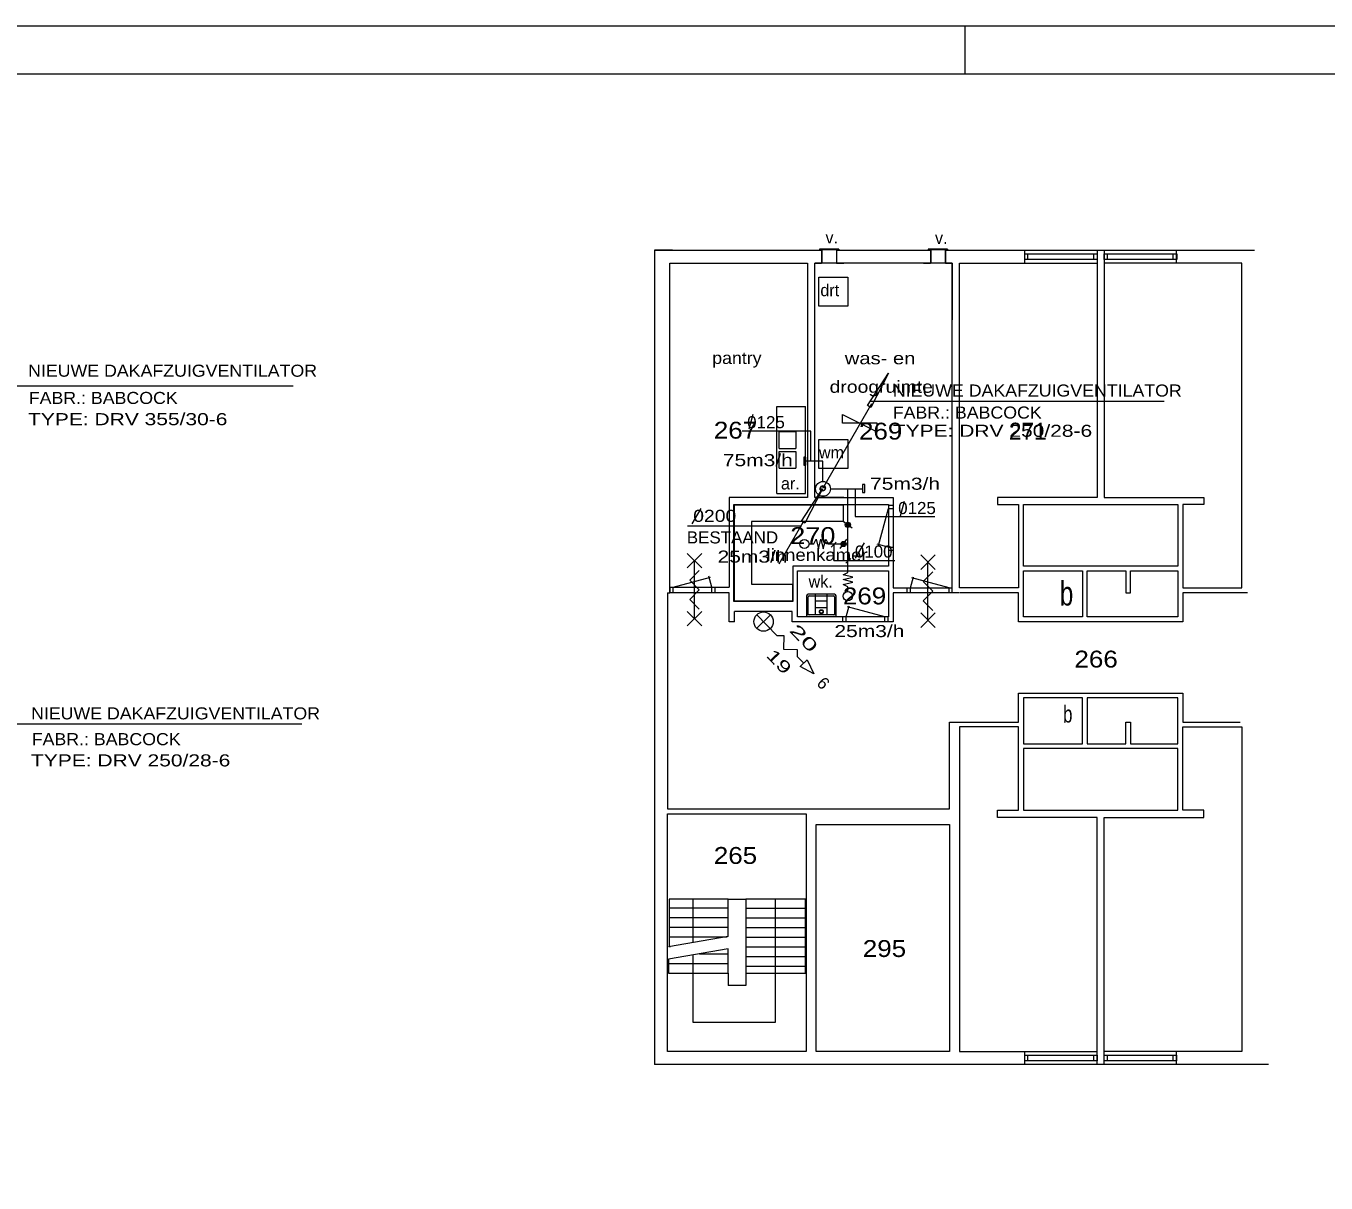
# Model space of a CAD drawing. Extents: x 295824 to 414724, y 24924 to 109024.
# Drawn here: x 332262 to 359197, y 85056 to 109024 of the extents above; entities that cross this region are included whole.
import ezdxf
from ezdxf.enums import TextEntityAlignment as Align

# ---------------------------------------------------------------- set-up
doc = ezdxf.new("R2010")
doc.units = 0
doc.header["$LTSCALE"] = 100
for name, color, linetype, lineweight in [('1', 7, 'Continuous', 13), ('24', 7, 'Continuous', 13), ('61', 7, 'Continuous', 13)]:
    doc.layers.add(name, color=color, linetype=linetype, lineweight=lineweight)

msp = doc.modelspace()

# ---------------------------------------------------------------- hatches: boundary and pattern name
at = {"layer": '24'}
for points in [[(349236.3, 98689.8, 1), (349344.9, 98689.8, 1)], [(349201, 98347.3, 1), (349201, 98238.7, 1)]]:
    msp.add_hatch(color=256, dxfattribs=at).paths.add_polyline_path(points)

# ---------------------------------------------------------------- linework, layer by layer
at = {"layer": '1'}
for p, q in [((351723.6, 108023.8), (351723.6, 109023.8)), ((347864.2, 97878.8), (348364.2, 98744.8))]:
    msp.add_line(p, q, dxfattribs=at)
for points in [[(414723.6, 109023.8), (304995.6, 109023.8), (295823.6, 109023.8)], [(304995.6, 25923.8), (413723.6, 25923.8), (413723.6, 108023.8), (304995.6, 108023.8)]]:
    msp.add_lwpolyline(points, dxfattribs=at)
msp.add_lwpolyline([(348764.2, 99437.8), (348400.2, 98723.8), (348328.2, 98765.8)], close=True, dxfattribs=at)
for centre in [(348764.2, 99437.5), (348777, 99453.9)]:
    msp.add_circle(centre, 50, dxfattribs=at)
at = {"layer": '24'}
for p, q in [((329942.6, 101572.7), (337794.9, 101572.7)), ((348777, 99454.2), (349787.6, 101204.5)), ((349752.7, 101252.7), (355843, 101252.7)), ((347322.1, 100977.4), (347240, 100670.9)), ((348774.2, 100005.9), (348418.4, 100005.9)), ((348774.2, 99588.7), (348774.2, 100005.9)), ((348927.8, 99435.2), (349590.4, 99435.2)), ((349290.6, 97754.4), (349290.6, 99435.2)), ((350459, 99175.8), (350376.9, 98869.3)), ((346240.6, 99028.4), (346056.3, 98709.1)), ((345969.4, 98666.6), (348330.2, 98666.6)), ((349382.2, 98619), (349190.6, 98760.6)), ((349047.8, 98330), (348945.6, 98227.8)), ((349130.2, 98201.4), (349271.8, 98392.9)), ((349629.1, 98320.4), (349444.7, 98001.1)), ((348931.9, 98293), (349290.6, 98293)), ((349350.5, 97995.7), (349248.3, 97893.4)), ((330003.8, 94565.6), (337978.3, 94565.6))]:
    msp.add_line(p, q, dxfattribs=at)
for points in [[(350133, 101831.4), (349769, 101117.4), (349697, 101159.4)], [(349898, 100614.9), (349898, 100794.9), (349178, 100794.9), (349178, 100974.9)], [(348418.4, 100089.3), (348374.9, 100089.3), (348374.9, 99927), (348418.4, 99927)], [(349640.4, 99522.6), (349596.9, 99522.6), (349596.9, 99360.3), (349640.4, 99360.3)]]:
    msp.add_lwpolyline(points, close=True, dxfattribs=at)
for points in [[(348525, 100017.6), (348525, 100631.2), (347102, 100631.2)], [(349440.9, 99431.4), (349440.9, 98865), (351091.9, 98865)], [(348481.9, 98293), (348581.9, 98293), (348631.9, 98393), (348681.9, 98193), (348731.9, 98393), (348781.9, 98193), (348831.9, 98393), (348881.9, 98293), (348931.9, 98293)], [(349000.7, 98290.7), (349000.7, 97952.4), (350266.4, 97952.4)], [(349290.6, 97304.4), (349290.6, 97404.4), (349190.6, 97454.4), (349390.6, 97504.4), (349190.6, 97554.4), (349390.6, 97604.4), (349190.6, 97654.4), (349290.6, 97704.4), (349290.6, 97754.4)]]:
    msp.add_lwpolyline(points, dxfattribs=at)
for centre, radius in [((348774.2, 99435.2), 153.6), ((349290.6, 98689.8), 54.3), ((348390.2, 98293), 95), ((349201, 98293), 54.3), ((349290.6, 97212.7), 95)]:
    msp.add_circle(centre, radius, dxfattribs=at)
at = {"layer": '61'}
for p, q in [((345284, 104378.8), (345284, 87509.4)), ((345654, 104378.8), (345284, 104378.8)), ((345284, 104378.8), (348747.5, 104378.8)), ((349101.1, 104400.3), (348702.8, 104400.3)), ((348702.8, 104400.3), (348702.8, 104385.2)), ((349101.1, 104385.2), (348702.8, 104385.2)), ((348747.5, 104378.8), (348747.5, 104110.1)), ((348753.1, 104385.2), (348753.1, 104110.9)), ((349051.8, 104385.2), (349051.8, 104110.9)), ((349058.2, 104378.8), (349058.2, 104110.4)), ((349058.2, 104378.8), (351001.2, 104378.8)), ((349101.1, 104400.3), (349101.1, 104385.2)), ((351354.8, 104400.3), (350956.5, 104400.3)), ((350956.5, 104400.3), (350956.5, 104385.2)), ((351354.8, 104385.2), (350956.5, 104385.2)), ((351001.2, 104378.8), (351001.2, 104110.4)), ((351006.8, 104385.2), (351006.8, 104110.9)), ((351305.5, 104385.2), (351305.5, 104110.9)), ((351311.9, 104378.8), (351311.9, 104108.8)), ((351311.9, 104378.8), (357714.4, 104378.8)), ((351354.8, 104400.3), (351354.8, 104385.2)), ((352953.9, 104111.8), (352953.9, 104381.8)), ((353020.7, 104190.1), (353020.7, 104303.9)), ((354385.7, 104189.5), (354385.7, 104303.5)), ((354669.2, 104190.4), (354669.2, 104304.4)), ((356033.5, 104190.1), (356033.5, 104303.8)), ((356102, 104111.8), (356102, 104382)), ((345604, 97284), (345604, 104108.8)), ((348604, 104110.1), (348747.5, 104110.1)), ((351454, 104108.8), (348604, 104108.8)), ((349051.8, 104110.9), (348753.1, 104110.9)), ((349058.2, 104110.4), (349204, 104110.4)), ((350854.5, 104110.4), (351001.2, 104110.4)), ((351305.5, 104110.9), (351006.8, 104110.9)), ((351604, 104108.8), (354454, 104108.8)), ((357454, 104108.8), (354604, 104108.8)), ((347864.1, 100620.5), (348214.1, 100620.5)), ((348215, 100618.8), (348215, 100268.8)), ((348214.1, 100266.4), (347864.1, 100266.4)), ((347864.1, 100212.3), (348214.1, 100212.3)), ((348215, 100210.6), (348215, 99860.6)), ((348214.1, 99858.2), (347864.1, 99858.2)), ((346929, 97103.8), (346929, 99108.8)), ((350127, 99024.6), (349919.9, 98251.8)), ((350228.5, 99090.8), (350127.6, 99090.8)), ((350226.5, 99023.8), (350128.9, 99023.8)), ((350226.9, 99090.8), (350130.2, 99090.8)), ((346262.8, 98096.2), (345962.8, 97796.2)), ((345962.8, 98096.2), (346262.8, 97796.2)), ((350126.4, 98226.2), (349899.5, 98286.9)), ((350226.2, 98223.8), (350127.6, 98223.8)), ((350226.5, 98156.8), (350127.6, 98156.8)), ((351099, 98066.6), (350799, 97766.6)), ((350799, 98066.6), (351099, 97766.6)), ((346112.8, 96746.2), (346112.8, 97946.2)), ((350949, 96716.6), (350949, 97916.6)), ((345672.2, 97398.6), (346444.9, 97605.7)), ((346470.6, 97399.3), (346409.8, 97626.1)), ((350588.1, 97384.9), (350648.9, 97611.8)), ((351386.5, 97384.3), (350613.8, 97591.3)), ((345554, 97284), (345604, 97284)), ((345673, 97284), (345673, 97398)), ((346473, 97284), (346473, 97398)), ((346540, 97284), (346540, 97398)), ((346829, 96683.8), (346829, 97284)), ((349010.5, 97250.8), (348470.5, 97250.8)), ((348620.5, 96825.8), (348620.5, 97250.8)), ((348860.5, 96825.8), (348860.5, 97250.8)), ((350229, 97283.8), (350229, 96683.8)), ((351600.1, 97283.8), (350229, 97283.8)), ((350518.8, 97284.8), (350518.8, 97383.7)), ((350585.8, 97285), (350585.8, 97383.7)), ((351385.8, 97284.8), (351385.8, 97383.7)), ((351452.8, 97284.8), (351452.8, 97383.7)), ((352829, 97283.8), (351615.2, 97283.8)), ((348149, 97103.8), (346929, 97103.8)), ((348435.5, 97215.8), (348435.5, 96800.8)), ((348470.5, 96840.8), (348470.5, 97200.8)), ((348485.5, 97215.8), (348995.5, 97215.8)), ((348860.5, 97109.1), (348620.5, 97109.1)), ((348860.5, 96967.5), (348620.5, 96967.5)), ((349010.5, 97200.8), (349010.5, 96840.8)), ((349045.5, 96800.8), (349045.5, 97215.8)), ((349258.4, 96783.9), (349319.2, 97010.8)), ((350056.8, 96783.3), (349284.1, 96990.3)), ((346262.8, 96896.2), (345962.8, 96596.2)), ((345962.8, 96896.2), (346262.8, 96596.2)), ((348139, 96893.8), (346939, 96893.8)), ((346939, 96683.8), (346939, 96893.8)), ((347687.6, 96823.5), (347399.9, 96545.7)), ((348139, 96683.8), (348139, 96893.8)), ((349035.5, 96825.8), (348445.5, 96825.8)), ((348445.5, 96790.8), (349035.5, 96790.8)), ((349189, 96683.8), (349189, 96782.7)), ((349256, 96684), (349256, 96782.7)), ((350056, 96683.8), (350056, 96782.7)), ((350123, 96683.8), (350123, 96782.7)), ((351099, 96866.6), (350799, 96566.6)), ((350799, 96866.6), (351099, 96566.6)), ((346939, 96683.8), (346829, 96683.8)), ((350229, 96683.8), (348139, 96683.8)), ((346088, 90036.5), (346088, 90933.3)), ((346809.5, 90933.3), (347175.2, 90938.7)), ((348415.1, 90938.7), (347175.2, 90938.7)), ((345586.7, 90755.8), (346809.5, 90755.8)), ((345586.7, 90555.8), (346809.5, 90555.8)), ((348415.1, 90738.7), (347175.2, 90738.7)), ((348415.1, 90538.7), (347175.2, 90538.7)), ((345586.7, 90355.8), (346809.5, 90355.8)), ((348415.1, 90338.7), (347175.2, 90338.7)), ((346811.5, 90159.7), (345571.7, 89948.5)), ((345586.7, 90155.8), (346788.3, 90155.8)), ((348415.1, 90138.7), (347175.2, 90138.7)), ((346811.5, 89903.1), (345571.7, 89691.9)), ((345586.7, 89955.8), (345614.2, 89955.8)), ((345586.7, 89955.8), (345614.2, 89955.8)), ((346219.8, 89802.3), (346811.5, 89802.3)), ((348415.1, 89938.7), (347175.2, 89938.7)), ((348415.1, 89738.7), (347175.2, 89738.7)), ((345571.7, 89691.9), (345571.7, 89402.3)), ((345571.7, 89602.3), (346811.5, 89602.3)), ((348415.1, 89538.7), (347175.2, 89538.7)), ((345571.7, 89402.3), (346811.5, 89402.3)), ((346811.5, 89402.3), (346811.5, 89144.4)), ((347175.2, 89402.3), (347175.2, 89144.4)), ((347175.2, 89144.4), (346811.5, 89144.4)), ((351604, 87779.4), (354454, 87779.4)), ((352953.9, 87509.2), (352953.9, 87779.2)), ((353020.7, 87587.5), (353020.7, 87701.3)), ((354385.7, 87586.9), (354385.7, 87700.9)), ((357454, 87779.4), (354604, 87779.4)), ((354669.2, 87587.8), (354669.2, 87701.8)), ((356033.5, 87587.5), (356033.5, 87701.2)), ((356102, 87509.2), (356102, 87779.4)), ((358007.8, 87509.4), (345284, 87509.4))]:
    msp.add_line(p, q, dxfattribs=at)
for points in [[(354454, 104378.8), (354454, 99258.8), (352394, 99258.8), (352394, 99108.8), (352829, 99108.8), (352829, 97383.8), (351604, 97383.8), (351604, 104108.8)], [(354604, 104378.8), (354604, 99258.8), (356664, 99258.8), (356664, 99108.8), (356229, 99108.8), (356229, 97383.8), (357454, 97383.8), (357454, 104108.8)], [(345604, 104108.8), (348454, 104108.8), (348454, 99258.8), (346829, 99258.8), (346829, 97398)], [(349204, 99258.8), (348604, 99258.8), (348604, 104108.8)], [(348604, 99258.8), (350229, 99258.8), (350229, 97383.8), (351454, 97383.8), (351454, 104108.8)], [(351311.9, 104108.8), (351454, 104108.8), (351454, 102933.8)], [(347815.9, 99340.5), (348410.6, 99340.5), (348410.6, 101140.5)], [(347815.9, 99340.5), (347815.9, 101140.5), (348410.6, 101140.5)], [(347865, 100268.8), (347865, 100618.8), (347864.1, 100620.5)], [(347865, 99860.6), (347865, 100210.6), (347864.1, 100212.3)], [(346929, 99108.8), (350129, 99108.8), (350129, 97833.8), (348149, 97833.8), (348149, 97103.8)], [(346212.8, 96946.2), (346012.8, 97146.2), (346212.8, 97346.2), (346012.8, 97546.2), (346212.8, 97746.2)], [(351049, 96916.6), (350849, 97116.6), (351049, 97316.6), (350849, 97516.6), (351049, 97716.6)], [(345554, 97284), (345554, 92804.4), (351394, 92804.4), (351394, 94604.4)], [(345606, 97284), (345606, 97398), (346829, 97398)], [(346829, 97284), (345606, 97284), (345606, 97398)], [(357567.7, 97283.8), (356229, 97283.8), (356229, 96683.8), (352829, 96683.8), (352829, 97283.8)], [(347404.8, 96828.5), (347821.6, 96396.9), (347963, 96394.4), (347958.1, 96111.6), (348240.9, 96106.7), (348238.4, 95965.2), (348377.4, 95821.4)], [(351394, 94604.4), (352829, 94604.4), (352829, 95204.4), (356229, 95204.4), (356229, 94604.4), (357421, 94604.4)], [(354454, 87511.6), (354454, 92629.4), (352394, 92629.4), (352394, 92779.4), (352829, 92779.4), (352829, 94504.4), (351604, 94504.4), (351604, 87779.4)], [(354604, 87509.4), (354604, 92629.4), (356664, 92629.4), (356664, 92779.4), (356229, 92779.4), (356229, 94504.4), (357454, 94504.4), (357454, 87779.4)], [(346809.5, 90159.4), (346809.5, 90933.3), (345586.7, 90933.3), (345586.7, 89955.8)], [(347786.9, 90938.7), (347786.9, 88378.1), (346084.1, 88378.1), (346084.1, 89779.2)], [(345571.7, 89402.3), (346811.5, 89402.3), (346811.5, 89903.1)]]:
    msp.add_lwpolyline(points, dxfattribs=at)
for points in [[(352953.9, 104189.9), (352953.9, 104303.9), (354452.5, 104303.9), (354452.5, 104189.9)], [(354604.1, 104190.1), (354604.1, 104304.1), (356103.5, 104304.1), (356103.5, 104190.1)], [(348686.3, 103220.9), (348686.3, 103820.9), (349286.3, 103820.9), (349286.3, 103220.9)], [(348686.3, 99857.2), (348686.3, 100457.2), (349286.3, 100457.2), (349286.3, 99857.2)], [(346943.7, 97108.4), (346943.7, 99102), (349194.4, 99102), (349194.4, 98761.9), (347293.7, 98761.9), (347293.7, 97459.5), (348143.9, 97459.5), (348143.9, 97108.4)], [(352929, 99108.8), (356129, 99108.8), (356129, 97833.8), (352929, 97833.8)], [(348249, 97733.8), (350129, 97733.8), (350129, 96783.8), (348249, 96783.8)], [(352929, 97733.8), (354149, 97733.8), (354149, 96783.8), (352929, 96783.8)], [(354249, 97733.8), (355049, 97733.8), (355049, 97283.8), (355149, 97283.8), (355149, 97733.8), (356129, 97733.8), (356129, 96783.8), (354249, 96783.8)], [(348305.4, 95751.9), (348449.3, 95890.9), (348585.8, 95605.6)], [(352929, 94154.4), (354149, 94154.4), (354149, 95104.4), (352929, 95104.4)], [(354249, 94154.4), (355049, 94154.4), (355049, 94604.4), (355149, 94604.4), (355149, 94154.4), (356129, 94154.4), (356129, 95104.4), (354249, 95104.4)], [(352929, 92779.4), (356129, 92779.4), (356129, 94054.4), (352929, 94054.4)], [(345554, 92704.4), (348424, 92704.4), (348424, 87779.4), (345554, 87779.4)], [(348634, 92484.4), (351394, 92484.4), (351394, 87779.4), (348634, 87779.4)], [(347175.2, 89402.3), (348415.1, 89402.3), (348415.1, 90938.7), (347175.2, 90938.7)], [(352953.9, 87587.3), (352953.9, 87701.3), (354452.5, 87701.3), (354452.5, 87587.3)], [(354602.9, 87587.5), (354602.9, 87701.5), (356102.2, 87701.5), (356102.2, 87587.5)]]:
    msp.add_lwpolyline(points, close=True, dxfattribs=at)
for centre, radius in [((347543.8, 96684.6), 200), ((348740.5, 96890.8), 40), ((348740.5, 96890.8), 30)]:
    msp.add_circle(centre, radius, dxfattribs=at)
for centre, radius, start, end in [((348470.5, 97215.8), 35, 90, 180), ((349010.5, 97215.8), 35, 0, 90), ((348485.5, 97200.8), 15, 90, 180), ((348995.5, 97200.8), 15, 0, 90), ((348445.5, 96815.8), 10, 90, 180), ((348445.5, 96800.8), 10, 180, 270), ((348485.5, 96840.8), 15, 180, 270), ((348995.5, 96840.8), 15, 270, 0), ((349035.5, 96815.8), 10, 0, 90), ((349035.5, 96800.8), 10, 270, 0)]:
    msp.add_arc(centre, radius, start, end, dxfattribs=at)

# ---------------------------------------------------------------- texts
at = {"layer": '24'}
for s, width, p in [('NIEUWE DAKAFZUIGVENTILATOR', 1.1, (332306.2, 101758.2)), ('NIEUWE DAKAFZUIGVENTILATOR', 1.1, (350221.3, 101347.4)), ('FABR.: BABCOCK', 1.1, (332320.2, 101193.6)), ('TYPE: DRV 355/30-6', 1.3, (332304.5, 100753.9)), ('FABR.: BABCOCK', 1.1, (350221.3, 100891.1)), ('0125', 1.05, (347203.4, 100691.6)), ('TYPE: DRV 250/28-6', 1.3, (350221.3, 100513.4)), ('75m3/h', 1.3, (346700.3, 99904.8)), ('75m3/h', 1.3, (349750.7, 99417.1)), ('0125', 1.05, (350332.4, 98913.6)), ('0200', 1.2, (346086, 98751.2)), ('BESTAAND', 1.05, (345953.3, 98304.3)), ('25m3/h', 1.3, (346590.2, 97906.6)), ('0100', 1.05, (349435.1, 98011.7)), ('25m3/h', 1.3, (349011.7, 96364.6)), ('NIEUWE DAKAFZUIGVENTILATOR', 1.1, (332367.4, 94659.3)), ('FABR.: BABCOCK', 1.1, (332381.3, 94125.2)), ('TYPE: DRV 250/28-6', 1.3, (332365.6, 93685.6))]:
    msp.add_text(s, height=250, dxfattribs=dict(at, width=width)).set_placement(p)
at = {"layer": '61'}
for s, height, p in [('v.', 250, (348826.1, 104518.7)), ('v.', 250, (351095.4, 104508.6)), ('drt', 250, (348720.7, 103426.2)), ('271', 350, (352627.8, 100455.9)), ('wm', 250, (348691.3, 100065)), ('ar.', 250, (347904.3, 99422.9)), ('wk.', 250, (348476.2, 97391.7))]:
    msp.add_text(s, height=height, dxfattribs=at).set_placement(p)
for s, height, width, p in [('pantry', 250, 1.1, (346479.8, 102022.3)), ('was- en', 250, 1.25, (349226.4, 102016)), ('droogruimte', 250, 1.2, (348911.9, 101425.8)), ('267', 350, 1.15, (346512.8, 100475.6)), ('269', 350, 1.15, (349521.1, 100455.9)), ('270', 350, 1.2, (348095.8, 98291.6)), ('linnenkamer', 250, 1.15, (347605.2, 97943.9)), ('269', 350, 1.15, (349186.8, 97042.2)), ('266', 350, 1.15, (353984.5, 95733.8)), ('265', 350, 1.15, (346512.8, 91665.8)), ('295', 350, 1.15, (349599.8, 89737.6))]:
    msp.add_text(s, height=height, dxfattribs=dict(at, width=width)).set_placement(p)
at = {"layer": '61', "width": 0.75}
for height, p in [(500, (353822, 97018.3)), (350, (353846.1, 94593.8))]:
    msp.add_text('b', height=height, dxfattribs=at).set_placement(p, align=Align.CENTER)
at = {"layer": '61'}
for s, width, p in [('20', 1.75, (348063, 96490.3)), ('19', 1.5, (347581.6, 95970.2))]:
    msp.add_text(s, height=250, rotation=314, dxfattribs=dict(at, width=width)).set_placement(p)
msp.add_text('6', height=250, rotation=314, dxfattribs=at).set_placement((348627.9, 95390.3))

doc.saveas('drawing.dxf')
